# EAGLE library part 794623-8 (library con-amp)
MICRO MATE N LOK Dual Row, grid 1.5 mm Source: http://catalog.tycoelectronics.com .. ENG_CD_794623_F.pdf
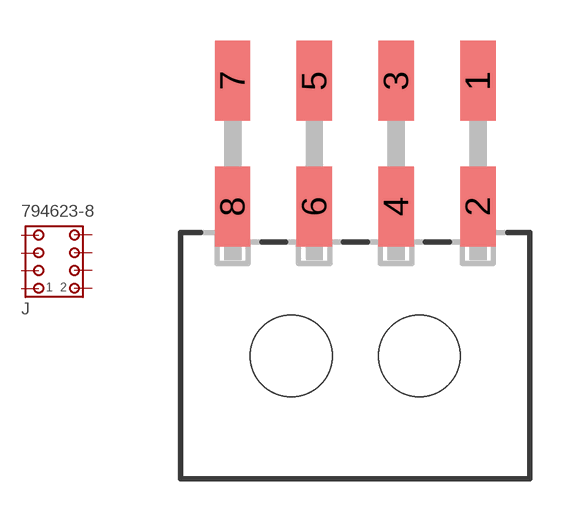
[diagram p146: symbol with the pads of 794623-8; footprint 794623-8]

Designator prefix J

## 794623-8 (MF: TYCO ELECTRONICS; MPN: 794623-8; OC_FARNELL: unknown; OC_NEWARK: 19H3721)  [794623-8]
1  1  pas
2  2  pas
3  3  pas
4  4  pas
5  5  pas
6  6  pas
7  7  pas
8  8  pas

## Footprint 794623-8 (pad centres in mm)
MICRO MATE N LOK Dual Row, grid 1.5 mm Source: http://catalog.tycoelectronics.com .. ENG_CD_794623_F.pdf
smd 1.3 x 2.92: 1 4.5,10.1; 2 4.5,5.48; 3 1.5,10.1; 4 1.5,5.48; 5 -1.5,10.1; 6 -1.5,5.48; 7 -4.5,10.1; 8 -4.5,5.48
hole 3 at -2.35,0
hole 3 at 2.35,0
